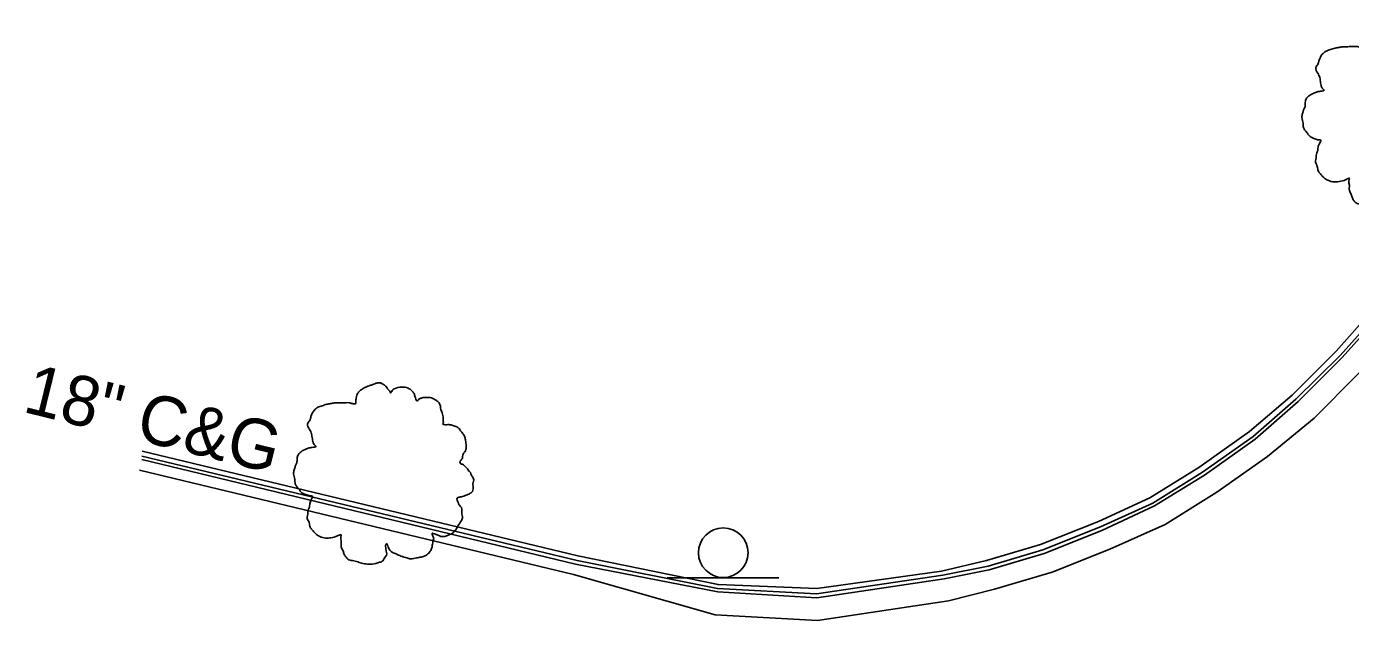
# Model space of a CAD drawing. Extents: x 2004847 to 2009016, y 1134161 to 1140101.
# Drawn here: x 2007509.7 to 2007616.3, y 1138413.2 to 1138461 of the extents above; entities that cross this region are included whole.
import ezdxf

# ---------------------------------------------------------------- set-up
doc = ezdxf.new("R2010")
doc.units = 0
for name, color, linetype in [('RD_EX_BldgApp', 7, 'Continuous'), ('RD_EX_Curb', 7, 'Continuous'), ('RD_EX_Road', 7, 'Continuous'), ('RD_EX_VEG', 7, 'Continuous'), ('RD_Sketch3', 7, 'Continuous')]:
    doc.layers.add(name, color=color, linetype=linetype)

msp = doc.modelspace()

# ---------------------------------------------------------------- linework, layer by layer
at = {"layer": 'RD_EX_BldgApp'}
msp.add_line((2007561.29, 1138416.64), (2007570.29, 1138416.64), dxfattribs=at)
msp.add_circle((2007565.8, 1138418.67), 2, dxfattribs=at)
at = {"layer": 'RD_EX_Curb'}
for points in [[(2007583.38, 1138417.19), (2007587.02, 1138418.05), (2007591.37, 1138419.33), (2007596.02, 1138421.17), (2007600.16, 1138423.09), (2007604.11, 1138425.53), (2007608.19, 1138428.42), (2007611.62, 1138431.36), (2007615.17, 1138434.89), (2007618.17, 1138438.23), (2007620.95, 1138441.93), (2007623.55, 1138446.2), (2007625.62, 1138450.26), (2007627.68, 1138454.81), (2007628.06, 1138455.93)], [(2007583.5, 1138416.86), (2007587.14, 1138417.6), (2007591.55, 1138418.9), (2007596.19, 1138420.74), (2007600.4, 1138422.67), (2007604.4, 1138425.14), (2007608.49, 1138428.01), (2007611.93, 1138431.04), (2007615.49, 1138434.55), (2007618.55, 1138437.94), (2007621.35, 1138441.68), (2007623.96, 1138445.95), (2007626.02, 1138450.08), (2007628.08, 1138454.63), (2007628.45, 1138455.83)], [(2007583.59, 1138416.56), (2007587.22, 1138417.3), (2007591.66, 1138418.61), (2007596.31, 1138420.45), (2007600.53, 1138422.43), (2007604.56, 1138424.92), (2007608.64, 1138427.81), (2007612.12, 1138430.84), (2007615.65, 1138434.38), (2007618.73, 1138437.8), (2007621.55, 1138441.56), (2007624.14, 1138445.84), (2007626.25, 1138449.97), (2007628.33, 1138454.52), (2007628.76, 1138455.75)], [(2007583.38, 1138417.19), (2007573.34, 1138415.78), (2007565.39, 1138416.11), (2007554.09, 1138418.43), (2007518.98, 1138426.84)], [(2007583.59, 1138416.56), (2007573.34, 1138415.05), (2007565.36, 1138415.53), (2007553.91, 1138417.76), (2007518.95, 1138426.18)], [(2007583.5, 1138416.86), (2007573.31, 1138415.37), (2007565.33, 1138415.8), (2007554.02, 1138418.05), (2007518.97, 1138426.43)]]:
    msp.add_lwpolyline(points, dxfattribs=at)
at = {"layer": 'RD_EX_Road'}
for points in [[(2007583.94, 1138414.79), (2007587.64, 1138415.73), (2007592.29, 1138417.1), (2007596.94, 1138418.95), (2007601.39, 1138420.95), (2007605.56, 1138423.53), (2007609.65, 1138426.4), (2007613.4, 1138429.51), (2007616.93, 1138433.05), (2007620.18, 1138436.67), (2007623.12, 1138440.59), (2007625.69, 1138444.89), (2007627.92, 1138449.22), (2007629.99, 1138453.77), (2007630.53, 1138455.28)], [(2007583.94, 1138414.79), (2007573.39, 1138413.22), (2007565.16, 1138413.66), (2007553.75, 1138416.92), (2007518.77, 1138425.3)]]:
    msp.add_lwpolyline(points, dxfattribs=at)
at = {"layer": 'RD_EX_VEG'}
for points in [[(2007619.49, 1138460.98), (2007619.19, 1138461.01), (2007618.86, 1138460.91), (2007618.61, 1138460.81), (2007618.39, 1138460.73), (2007618.16, 1138460.63), (2007617.86, 1138460.46), (2007617.64, 1138460.26), (2007617.51, 1138460.01), (2007617.46, 1138459.78), (2007617.41, 1138459.51), (2007617.41, 1138459.33), (2007617.29, 1138459.31), (2007617.14, 1138459.33), (2007616.89, 1138459.41), (2007616.64, 1138459.41), (2007616.39, 1138459.41), (2007616.04, 1138459.38), (2007615.69, 1138459.38), (2007615.41, 1138459.33), (2007615.09, 1138459.28), (2007614.71, 1138459.16), (2007614.36, 1138459.03), (2007614.06, 1138458.78), (2007613.81, 1138458.31), (2007613.69, 1138457.96), (2007613.54, 1138457.71), (2007613.69, 1138457.26), (2007613.86, 1138456.91), (2007613.89, 1138456.71), (2007613.96, 1138456.28), (2007614.06, 1138456.06), (2007614.19, 1138455.86), (2007614.11, 1138455.83), (2007613.74, 1138455.78), (2007613.44, 1138455.68), (2007613.02, 1138455.46), (2007612.79, 1138455.24), (2007612.69, 1138454.91), (2007612.67, 1138454.56), (2007612.57, 1138454.36), (2007612.49, 1138454.09), (2007612.47, 1138454.01), (2007612.42, 1138453.69), (2007612.52, 1138453.24), (2007612.54, 1138452.89), (2007612.67, 1138452.66), (2007612.82, 1138452.49), (2007612.99, 1138452.24), (2007613.39, 1138452.01), (2007613.71, 1138451.91), (2007613.91, 1138451.89), (2007613.74, 1138451.39), (2007613.69, 1138451.04), (2007613.57, 1138450.64), (2007613.57, 1138450.56), (2007613.52, 1138450.09), (2007613.66, 1138449.76), (2007613.74, 1138449.39), (2007613.91, 1138449.16), (2007614.19, 1138448.86), (2007614.51, 1138448.64), (2007615.01, 1138448.51), (2007615.41, 1138448.54), (2007615.99, 1138448.71), (2007616.24, 1138448.79), (2007616.21, 1138448.61), (2007616.24, 1138448.24), (2007616.24, 1138447.81), (2007616.39, 1138447.49), (2007616.49, 1138447.21), (2007616.64, 1138446.96), (2007616.96, 1138446.74), (2007617.36, 1138446.66), (2007617.79, 1138446.51), (2007618.24, 1138446.44), (2007618.74, 1138446.41), (2007619.34, 1138446.56), (2007619.61, 1138446.69), (2007619.71, 1138446.86), (2007619.91, 1138447.24), (2007619.86, 1138447.46), (2007619.89, 1138448.06), (2007619.99, 1138447.89), (2007620.16, 1138447.54), (2007620.66, 1138447.24), (2007621.06, 1138447.06), (2007621.54, 1138446.91), (2007621.84, 1138446.84), (2007622.31, 1138446.91), (2007622.69, 1138446.99), (2007623.06, 1138447.11), (2007623.36, 1138447.39), (2007623.54, 1138447.66), (2007623.59, 1138447.94), (2007623.66, 1138448.31), (2007623.71, 1138448.49)], [(2007538.27, 1138432.32), (2007537.97, 1138432.34), (2007537.64, 1138432.24), (2007537.39, 1138432.14), (2007537.17, 1138432.07), (2007536.94, 1138431.97), (2007536.64, 1138431.79), (2007536.42, 1138431.59), (2007536.29, 1138431.34), (2007536.24, 1138431.12), (2007536.19, 1138430.84), (2007536.19, 1138430.67), (2007536.07, 1138430.64), (2007535.92, 1138430.67), (2007535.67, 1138430.74), (2007535.42, 1138430.74), (2007535.17, 1138430.74), (2007534.82, 1138430.72), (2007534.47, 1138430.72), (2007534.19, 1138430.67), (2007533.87, 1138430.62), (2007533.49, 1138430.49), (2007533.14, 1138430.37), (2007532.84, 1138430.12), (2007532.59, 1138429.64), (2007532.47, 1138429.29), (2007532.32, 1138429.04), (2007532.47, 1138428.59), (2007532.64, 1138428.24), (2007532.67, 1138428.04), (2007532.74, 1138427.62), (2007532.84, 1138427.39), (2007532.97, 1138427.19), (2007532.89, 1138427.17), (2007532.52, 1138427.12), (2007532.22, 1138427.02), (2007531.79, 1138426.79), (2007531.57, 1138426.57), (2007531.47, 1138426.24), (2007531.44, 1138425.89), (2007531.34, 1138425.69), (2007531.27, 1138425.42), (2007531.24, 1138425.34), (2007531.19, 1138425.02), (2007531.29, 1138424.57), (2007531.32, 1138424.22), (2007531.44, 1138423.99), (2007531.59, 1138423.82), (2007531.77, 1138423.57), (2007532.17, 1138423.35), (2007532.49, 1138423.25), (2007532.69, 1138423.22), (2007532.52, 1138422.72), (2007532.47, 1138422.37), (2007532.34, 1138421.97), (2007532.34, 1138421.9), (2007532.29, 1138421.42), (2007532.44, 1138421.1), (2007532.52, 1138420.72), (2007532.69, 1138420.5), (2007532.97, 1138420.2), (2007533.29, 1138419.97), (2007533.79, 1138419.85), (2007534.19, 1138419.87), (2007534.77, 1138420.05), (2007535.02, 1138420.12), (2007534.99, 1138419.95), (2007535.02, 1138419.57), (2007535.02, 1138419.15), (2007535.17, 1138418.82), (2007535.27, 1138418.55), (2007535.42, 1138418.3), (2007535.74, 1138418.07), (2007536.14, 1138418), (2007536.57, 1138417.85), (2007537.02, 1138417.77), (2007537.52, 1138417.75), (2007538.12, 1138417.9), (2007538.39, 1138418.02), (2007538.49, 1138418.2), (2007538.69, 1138418.57), (2007538.64, 1138418.8), (2007538.67, 1138419.4), (2007538.77, 1138419.22), (2007538.94, 1138418.87), (2007539.44, 1138418.57), (2007539.84, 1138418.4), (2007540.31, 1138418.25), (2007540.61, 1138418.17), (2007541.09, 1138418.25), (2007541.46, 1138418.32), (2007541.84, 1138418.45), (2007542.14, 1138418.72), (2007542.31, 1138419), (2007542.36, 1138419.27), (2007542.44, 1138419.65), (2007542.49, 1138419.82)], [(2007542.49, 1138419.82), (2007542.41, 1138420), (2007542.36, 1138420.25), (2007542.44, 1138420.22), (2007542.61, 1138420.17), (2007542.89, 1138420.05), (2007543.11, 1138419.97), (2007543.44, 1138420), (2007543.71, 1138420.1), (2007544.16, 1138420.37), (2007544.44, 1138420.85), (2007544.71, 1138421.25), (2007544.79, 1138421.57), (2007544.74, 1138421.8), (2007544.71, 1138422.3), (2007544.51, 1138422.55), (2007544.46, 1138422.67), (2007544.36, 1138423.07), (2007544.44, 1138423.12), (2007544.71, 1138423.17), (2007545.09, 1138423.3), (2007545.36, 1138423.42), (2007545.59, 1138423.6), (2007545.66, 1138423.82), (2007545.64, 1138424.22), (2007545.69, 1138424.62), (2007545.61, 1138424.77), (2007545.51, 1138424.92), (2007545.44, 1138425.12), (2007545.29, 1138425.27), (2007545.19, 1138425.42), (2007545.09, 1138425.52), (2007544.96, 1138425.67), (2007544.79, 1138425.79), (2007544.64, 1138425.84), (2007544.59, 1138425.99), (2007544.74, 1138426.19), (2007544.79, 1138426.29), (2007544.81, 1138426.52), (2007545.04, 1138426.87), (2007545.09, 1138427.27), (2007545.04, 1138427.69), (2007544.99, 1138427.97), (2007544.84, 1138428.24), (2007544.64, 1138428.49), (2007544.51, 1138428.67), (2007544.34, 1138428.79), (2007544.01, 1138428.92), (2007543.76, 1138428.97), (2007543.41, 1138428.97), (2007543.21, 1138429.02), (2007543.24, 1138429.07), (2007543.24, 1138429.22), (2007543.24, 1138429.49), (2007543.16, 1138429.94), (2007543.01, 1138430.44), (2007543.01, 1138430.47), (2007542.91, 1138430.72), (2007542.69, 1138430.92), (2007542.51, 1138431.02), (2007542.31, 1138431.14), (2007542.06, 1138431.17), (2007541.76, 1138431.17), (2007541.49, 1138431.12), (2007541.29, 1138431.02), (2007541.11, 1138430.89), (2007541.04, 1138431.04), (2007540.94, 1138431.34), (2007540.89, 1138431.49), (2007540.74, 1138431.67), (2007540.51, 1138431.87), (2007540.06, 1138431.99), (2007539.44, 1138431.92), (2007539.14, 1138431.72), (2007538.99, 1138431.54), (2007538.94, 1138431.67), (2007538.74, 1138431.87), (2007538.64, 1138432.04), (2007538.47, 1138432.17), (2007538.32, 1138432.27), (2007538.22, 1138432.32)]]:
    msp.add_spline(points, degree=3, dxfattribs=at)

# ---------------------------------------------------------------- texts
at = {"layer": 'RD_Sketch3'}
msp.add_text('18" C&G', height=4, rotation=346.144, dxfattribs=at).set_placement((2007509.27, 1138430.03))

doc.saveas('drawing.dxf')
